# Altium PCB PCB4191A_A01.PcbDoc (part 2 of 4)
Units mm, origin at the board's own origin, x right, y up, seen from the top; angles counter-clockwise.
Board outline 160 x 160 mm, 6 copper layers (Top Layer, IM1 RIS, IM2 Signal, IM3 Signal, IM4 GND, Bottom Layer), stack 1.582 mm thick; 176 components, 121 nets, 494 pads, 4954 vias.
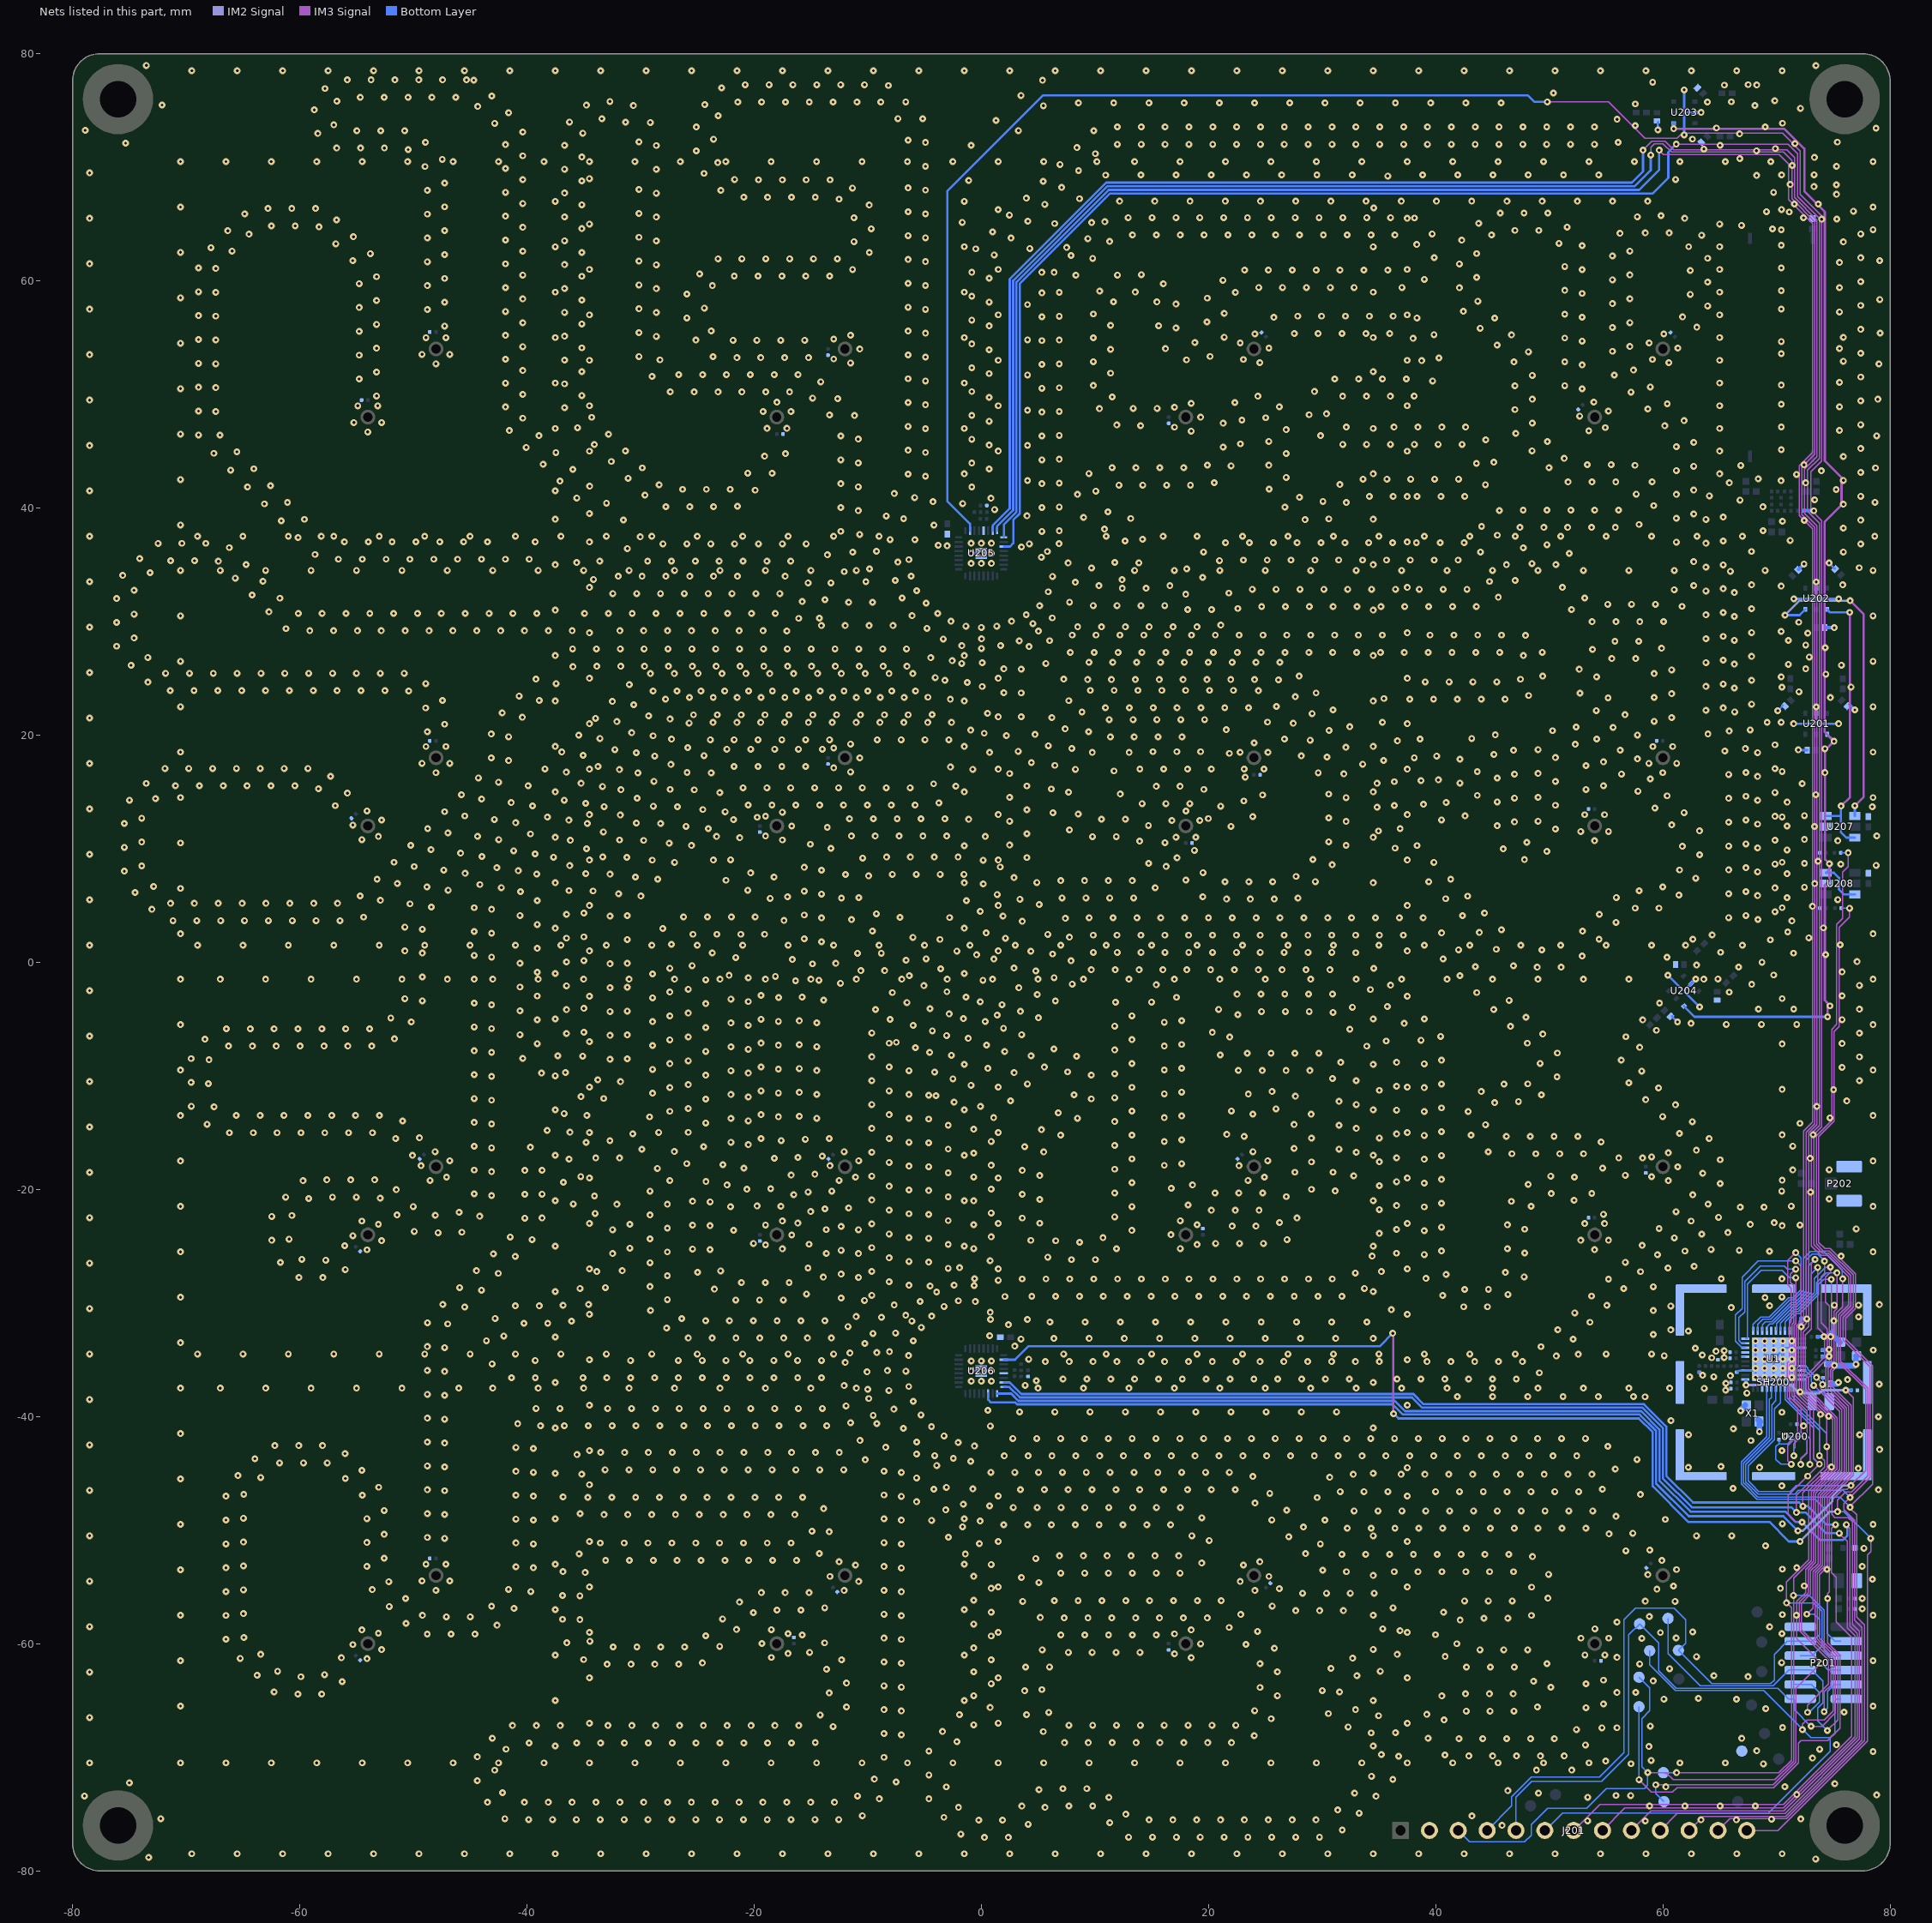
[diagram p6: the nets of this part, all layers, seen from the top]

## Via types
v1: diameter 0.6, hole 0.25, IM4 GND to Bottom Layer, tented bottom, 3924 vias
v2: diameter 0.6, hole 0.25, Top Layer to Bottom Layer, tented both sides, 851 vias
v3: diameter 0.6, hole 0.25, IM4 GND to Bottom Layer, tented both sides, 179 vias

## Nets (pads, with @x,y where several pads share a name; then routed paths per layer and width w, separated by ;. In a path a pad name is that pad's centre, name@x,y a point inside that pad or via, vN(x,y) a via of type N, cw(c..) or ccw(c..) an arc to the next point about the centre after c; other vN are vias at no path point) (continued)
CP/DP-: U201.4 U203.4 U204.4 U208.3 U208.6 | length 111
  IM3 Signal w0.2: v2(60.951,73.392) 70.683,73.392 72.45,71.625 72.45,67.876 74.251,66.075 74.251,44.149 75.725,42.675 75.725,40.25 74.23,38.755 74.23,20.291 v2(75.066,19.455) 74.275,18.665 74.275,9.044 v2(74.655,8.664) 74.655,7.192 74.25,6.787 74.25,-3.35 74.5,-3.6 v2(74.5,-4.8)
  Bottom Layer w0.2: U204.4@61.855,-3.866 62.788,-4.8 v2(74.5,-4.8) ; U201.4@74.45,20.071 v2(75.066,19.455) ; v2(74.655,8.664) 74.655,8.177 U208.3@74.355,7.878 75.06,7.878 75.496,7.441 75.496,6.41 75.933,5.973 U208.6@76.895,5.973
  Bottom Layer w0.35: v2(60.951,73.392) U203.4@60.951,73.875
CTRL1: J201.7 U1.1 U205.7 U206.7 | length 355.9
  IM3 Signal w0.1: J201.7@52.15,-76.45 54.45,-74.15 70.6,-74.15 76.6,-68.15 76.6,-59.45 75.25,-58.1 75.25,-54.15 74.854,-53.754 74.854,-49.871 v2@75.175,-49.55 ; v2(58.25,71.5) 59.025,72.275 60.2,72.275 60.95,71.525 70.925,71.525 71.6,70.85 71.6,67.325 73.568,65.357 73.568,44.518 72.475,43.425 72.475,39.525 73.568,38.432 73.568,-14.29 72.825,-15.033 72.825,-32.075 72.35,-32.55 72.35,-35.875 72.198,-36.027 72.198,-37.804 74.425,-40.03 v2(74.425,-42.65) ; v2(72.325,-47.9) 72.325,-46.725 74.45,-44.6 74.45,-42.922 v2@74.475,-42.897
  Bottom Layer w0.1: U1.1@71.55,-37.445 71.55,-38.625 74.425,-41.5 v2(74.425,-42.65)
  Bottom Layer w0.2: U205.7@1,37.985 1,38.45 2.5,39.95 2.5,60.138 11.012,68.65 57.275,68.65 58.25,69.625 v2(58.25,71.5) ; U206.7@1.985,-37 2.499,-37 3.524,-38.025 38.039,-38.025 38.929,-38.915 58.323,-38.915 60.303,-40.894 60.303,-45.228 62.65,-47.575 72,-47.575 v2(72.325,-47.9) 72.775,-47.9 74.4,-49.525 v2(75.2,-49.525)
CTRL2: J201.8 U1.2 U205.8 U206.8 | length 354
  IM3 Signal w0.1: J201.8@54.69,-76.45 56.665,-74.475 70.617,-74.475 76.9,-68.192 76.9,-59.3 76.225,-58.625 76.225,-51 v2@75.5,-50.275 ; v2(58.925,71.075) 58.95,71.1 58.95,71.75 59.25,72.05 60.025,72.05 60.75,71.325 70.625,71.325 71.35,70.6 71.35,67.225 73.368,65.207 73.368,44.725 72.25,43.607 72.25,39.4 73.368,38.282 73.368,-14.207 72.6,-14.975 72.6,-31.825 72.15,-32.275 72.15,-35.75 71.998,-35.902 71.998,-37.887 73.775,-39.663 73.775,-43.441 v2(73.782,-43.448) 73.798,-43.448 74.25,-43.9 74.25,-44.45 71.75,-46.95 v2(71.75,-48.45)
  Bottom Layer w0.1: U1.2@71.15,-37.445 71.15,-38.6 73.775,-41.225 v2@73.775,-43.45
  Bottom Layer w0.2: U205.8@1.4,37.985 1.4,38.4 2.8,39.8 2.8,60.014 11.111,68.325 57.525,68.325 58.925,69.725 v2(58.925,71.075) ; U206.8@1.985,-37.4 2.475,-37.4 3.399,-38.325 36.117,-38.325 37.915,-38.325 38.805,-39.215 58.199,-39.215 60.003,-41.018 60.003,-45.453 62.55,-48 71.3,-48 v2(71.75,-48.45) 72.55,-48.45 74.375,-50.275 v2(75.525,-50.275)
CTRL3: J201.9 U1.3 U205.9 U206.9 | length 356.4
  IM3 Signal w0.1: J201.9@57.23,-76.45 58.955,-74.725 70.65,-74.725 77.1,-68.275 77.1,-59.1 76.475,-58.475 76.475,-49.85 v2(76.15,-49.525) ; v2(59.675,71.5) 60.05,71.125 70.25,71.125 71.075,70.3 71.075,67.15 73.168,65.057 73.168,44.9 72,43.732 72,39.325 73.168,38.157 73.168,-14.082 72.4,-14.85 72.4,-31.7 71.95,-32.15 71.95,-35.625 71.798,-35.777 71.798,-37.969 73.25,-39.421 73.25,-43.66 v2(73.782,-44.192) 71.025,-46.949 71.025,-48.625 71.7,-49.3 v2(72.25,-49.3)
  Bottom Layer w0.1: U1.3@70.75,-37.445 70.75,-38.5 73.25,-41 73.25,-43.7 v2@73.75,-44.2
  Bottom Layer w0.2: U206.9@1.4,-37.985 2.635,-37.985 3.275,-38.625 36.4,-38.625 37.3,-39.525 58.085,-39.525 59.703,-41.142 59.703,-45.653 62.425,-48.375 70.775,-48.375 71.7,-49.3 v2(72.25,-49.3) 73.825,-50.875 75.85,-50.875 76.225,-50.5 76.225,-49.625 76.15,-49.55 v2(76.15,-49.525) ; U205.9@1.985,37.4 1.985,38.535 3.1,39.65 3.1,59.89 11.21,68 57.9,68 59.675,69.775 v2(59.675,71.5)
CTRL4: J201.10 U1.4 U205.11 U206.11 | length 372.8
  IM3 Signal w0.1: J201.10@59.77,-76.45 61.27,-74.95 70.75,-74.95 77.3,-68.4 77.3,-58.925 76.675,-58.3 76.675,-49.25 76.325,-48.9 75.15,-48.9 74.875,-48.625 74.875,-47.375 75.825,-46.425 76.2,-46.425 v2(76.55,-46.075) 76.55,-46.05 77.854,-44.746 77.854,-37.604 75.45,-35.2 75.45,-31.075 76.35,-30.175 76.35,-27.683 74.492,-25.825 73.925,-25.825 73.075,-24.975 73.075,-15.075 73.768,-14.382 73.768,38.657 72.725,39.7 72.725,43.332 73.768,44.375 73.768,65.507 71.85,67.425 71.85,71.2 71.025,72.025 v2(61.175,72.025)
  IM2 Signal w0.2: v2(71.888,-50.063) 72.312,-50.063 74.925,-47.45 74.925,-47.02 75.87,-46.075 v2(76.55,-46.075)
  Bottom Layer w0.1: U1.4@70.35,-37.445 70.35,-38.785 69.83,-39.306 69.83,-42.032 67.51,-44.352 67.51,-45.678 67.847,-46.015 68.431,-46.6 71.225,-46.6 71.75,-46.075 v2(76.55,-46.075)
  Bottom Layer w0.2: U206.11@0.6,-37.985 0.6,-38.525 0.841,-38.766 2.992,-38.766 3.151,-38.925 36.225,-38.925 37.125,-39.825 57.961,-39.825 59.403,-41.267 59.403,-45.903 62.275,-48.775 70.6,-48.775 v2(71.888,-50.063) ; U205.11@1.985,36.6 2.525,36.6 2.82,36.895 2.82,38.945 3.4,39.525 3.4,59.765 11.309,67.675 59.075,67.675 60.475,69.075 60.475,71.325 v2(61.175,72.025)
CTRL5: J201.11 R206.1 U1.5 | length 122.5
  IM3 Signal w0.1: J201.11@62.31,-76.45 63.56,-75.2 70.809,-75.2 77.525,-68.484 77.525,-58.575 76.875,-57.925 76.875,-49.125 75.925,-48.175 75.925,-47.675 v2(76.475,-47.125) ; v2(76.313,9.639) 76.313,8.413 75.837,7.938 75.837,3.862 75.3,3.325 75.3,-5.475 74.86,-5.915 74.86,-13.93 73.5,-15.29 73.5,-24.8 74.125,-25.425 74.658,-25.425 76.75,-27.517 76.75,-30.392 75.85,-31.292 75.85,-33.233 76.817,-34.2 78.254,-35.636 78.254,-45.371 v2@76.475,-47.15
  Bottom Layer w0.1: U1.5@69.95,-37.445 69.95,-38.623 69.604,-38.97 69.604,-41.921 67.31,-44.216 67.31,-45.761 67.537,-45.989 67.626,-46.077 68.369,-46.821 71.629,-46.821 71.95,-46.5 75.85,-46.5 v2@76.45,-47.1 ; R206.1@75.655,9.639 v2(76.313,9.639)
CTRL5+: U202.6 U207.4 | length 28
  IM3 Signal w0.2: v2(76.481,31.837) 77.675,30.643 77.675,14.559 v2(76.895,13.779)
  IM2 Signal w0.2: v2(70.758,30.566) 72.029,31.837 v2(76.481,31.837)
  Bottom Layer w0.2: v2(70.758,30.566) 72.045,30.566 U202.6@72.55,31.071 ; U207.4@76.895,12.878 v2(76.895,13.779)
CTRL5-: U202.4 U207.3 U207.6 | length 24.5
  IM3 Signal w0.2: v2(75.689,13.752) 76.47,14.534 v2@76.47,30.807
  Bottom Layer w0.2: U207.3@74.355,12.878 75.66,12.878 ; U202.4@74.45,31.071 74.715,30.807 v2(76.442,30.807) ; v2(75.689,13.752) 75.66,13.723 75.66,12.878 ; U207.6@76.895,10.973 76.153,10.973 75.66,11.465 75.66,12.878
CTRL6: J201.12 R207.1 U1.6 | length 115.3
  IM3 Signal w0.1: J201.12@64.85,-76.45 65.9,-75.4 70.892,-75.4 77.75,-68.542 77.75,-58.35 77.075,-57.675 77.075,-48.662 76.475,-48.062 v2(76.475,-48) 76.475,-47.938 78.454,-45.959 78.454,-35.554 76.9,-34 76.075,-33.175 76.075,-31.375 76.95,-30.5 76.95,-27.434 74.741,-25.225 74.275,-25.225 73.725,-24.675 73.725,-15.348 75.06,-14.013 75.06,-6.115 75.525,-5.65 75.525,3.05 76.435,3.96 v2(76.435,4.76)
  Bottom Layer w0.1: U1.6@69.55,-37.445 69.55,-38.329 69.373,-38.506 69.373,-41.851 67.11,-44.114 67.11,-45.844 67.245,-45.979 68.348,-47.082 75.582,-47.082 76.475,-47.975 v2(76.475,-48) ; R207.1@75.694,4.76 v2(76.435,4.76)
CTRL7: J201.13 U1.7 U205.2 U206.2 | length 382.4
  IM3 Signal w0.1: v2(49.825,75.75) 55.225,75.75 58.425,72.55 61.25,72.55 61.7,73 70.525,73 72.1,71.425 72.1,67.605 73.98,65.725 73.98,44.125 73.025,43.17 73.025,39.85 73.98,38.895 73.98,-14.47 73.275,-15.175 73.275,-24.858 74.042,-25.625 74.575,-25.625 76.55,-27.6 76.55,-30.275 75.65,-31.175 75.65,-35.117 78.054,-37.521 78.054,-45.221 76.625,-46.65 76.1,-46.65 75.375,-47.375 v2(75.375,-48.375) ; J201.13@67.39,-76.45 J201.13@67.392,-76.45 70.125,-76.45 78,-68.575 78,-52.2 78.3,-51.9 v2(78.3,-50.725)
  IM3 Signal w0.2: v2(36.225,-32.675) 36.275,-32.725 36.275,-39.725 v2(36.3,-39.75)
  IM2 Signal w0.2: v2(72.075,-51) 74.7,-48.375 v2(75.375,-48.375)
  Bottom Layer w0.1: U1.7@69.15,-37.445 69.15,-41.765 66.91,-44.006 66.91,-45.927 68.286,-47.303 73.411,-47.303 74.484,-48.375 v2(75.375,-48.375) 75.95,-48.375 v2(78.3,-50.725)
  Bottom Layer w0.2: U205.2@-1,37.985 -1,38.6 -3.001,40.6 -3.001,67.894 5.443,76.338 48.113,76.338 48.7,75.75 v2(49.825,75.75) ; U206.2@1.985,-35 2.973,-35 4.174,-33.8 35.1,-33.8 v2(36.225,-32.675) ; v2(36.3,-39.75) 36.725,-40.175 57.887,-40.175 59.103,-41.391 59.103,-46.153 62.225,-49.275 69.375,-49.275 71.1,-51 v2(72.075,-51)
EFR32_#RESET: C208.1 P201.3 TPJ17.1 U1.11 | length 74.1
  IM3 Signal w0.1: v2(57.899,-71.975) 58.999,-73.075 60.85,-73.075 61.25,-72.675 69.751,-72.675 71.923,-70.503 71.923,-68.767 72.142,-68.548 74.487,-68.548 75.593,-67.441 75.593,-61.016 74.5,-59.923 v2(74.5,-56.023) 74.5,-55.607 74.654,-55.453 74.654,-47.271 76.758,-45.167 76.758,-38.338 v2(76.105,-37.686)
  IM2 Signal w0.2: v2(67.325,-37.231) 71.281,-37.231 72,-37.95 73.775,-37.95 74.039,-37.686 v2(76.105,-37.686)
  Bottom Layer w0.1: v2(57.899,-71.975) TPJ17.1@57.899,-65.557 ; v2(74.5,-56.023) 74.459,-56.064 74.459,-59.117 75.124,-59.782 P201.3@75.657,-59.782 ; C208.1@76.577,-37.686 C208.1@76.615,-37.648
  Bottom Layer w0.3: v2(67.325,-37.231) 67.325,-37.226 67.4,-37.151 67.325,-37.076 U1.11@67.325,-36.842 ; v2(76.105,-37.686) C208.1@76.577,-37.686
EFR32_PA00: R205.1 U1.21 U200.A3 | length 34.1
  IM3 Signal w0.1: v2@71.275,-44.175 71,-43.9 71,-42.575 71.875,-41.7 71.875,-39.3 70.95,-38.375 70.95,-35.3 71.125,-35.125 71.125,-31.826 71.3,-31.651 71.3,-28.7 70.975,-28.375 70.975,-26.275 71.675,-25.575 v2(71.7,-25.575)
  Bottom Layer w0.1: U1.21@67.95,-32.455 67.95,-31.9 68.601,-31.25 69.375,-31.25 71.077,-29.548 71.452,-29.548 72.175,-28.825 72.175,-26.05 v2(71.7,-25.575) ; 70.225,-42.35 R205.1@70.225,-42.025 ; U200.A3@71.25,-42.125 70.975,-42.4 70.225,-42.4 70.225,-42.375 69.95,-42.65 69.95,-43.775 70.375,-44.2 v2(71.3,-44.2)
EFR32_PA01: P201.8 TPJ2.1 U1.22 | length 80.6
  IM3 Signal w0.1: v2(74.474,-67.643) 75.393,-66.724 75.393,-61.099 73.8,-59.506 73.8,-53.915 74.454,-53.261 74.454,-47.188 76.558,-45.084 76.558,-39.008 74.95,-37.4 74.95,-35.975 75.25,-35.675 75.25,-30.9 75.825,-30.325 v2(75.825,-27.875) 75.8,-27.875 v2@75.775,-27.85
  Bottom Layer w0.1: TPJ2.1@60.449,-57.777 60.449,-60.876 63.293,-63.719 69.688,-63.719 71.086,-62.322 P201.8@72.093,-62.322 73.107,-62.322 74.082,-63.296 74.082,-65.232 73.628,-65.686 73.628,-66.797 v2(74.474,-67.643) ; U1.22@68.35,-32.455 68.35,-31.9 68.8,-31.45 69.475,-31.45 71.177,-29.748 71.534,-29.748 72.4,-28.883 72.4,-26.075 73,-25.475 74.175,-25.475 75.8,-27.1 75.8,-27.875 v2(75.825,-27.875)
EFR32_PA02: P201.7 TPJ1.1 U1.23 | length 76.8
  IM3 Signal w0.1: v2(59.375,-72.425) 69.715,-72.425 69.716,-72.427 71.714,-70.429 71.714,-63.937 v2(73.908,-61.742) 73.908,-61.679 71.79,-59.56 71.79,-56.273 72.56,-55.504 72.56,-53.458 73.254,-52.764 73.254,-46.691 75.344,-44.601 75.344,-40.099 72.8,-37.555 72.8,-36.55 74.45,-34.9 74.45,-32.275 73.925,-31.75 73.925,-27.7 74.225,-27.4 v2(74.225,-26.325)
  Bottom Layer w0.1: v2(59.375,-72.425) 59.375,-73.185 TPJ1.1@60.098,-73.907 ; U1.23@68.75,-32.455 68.75,-31.917 69.018,-31.65 69.575,-31.65 71.277,-29.948 71.617,-29.948 72.625,-28.941 72.625,-26.225 73.15,-25.7 73.625,-25.7 74.225,-26.3 v2(74.225,-26.325) ; v2(73.908,-61.742) 73.972,-61.742 74.551,-62.322 P201.7@75.657,-62.322
EFR32_PA03: P201.6 TPJ3.1 U1.24 | length 76.2
  IM3 Signal w0.1: v2@61.205,-71.377 70.198,-71.377 71.312,-70.263 71.312,-56.851 v2(70.88,-56.418) 70.88,-54.57 72.852,-52.598 72.852,-46.525 74.942,-44.435 74.942,-40.265 72.398,-37.721 72.398,-36.202 72.55,-36.05 72.55,-32.825 73.075,-32.3 73.075,-26.5 v2(73.4,-26.175)
  Bottom Layer w0.1: TPJ3.1@60.049,-71.357 v2(61.205,-71.357) ; U1.24@69.15,-32.455 69.2,-32.405 69.2,-32.05 69.4,-31.85 69.675,-31.85 71.377,-30.148 71.7,-30.148 72.85,-28.999 72.85,-26.725 v2(73.4,-26.175) ; v2(70.88,-56.418) 73.259,-56.418 73.993,-57.151 73.993,-60.182 73.123,-61.052 P201.6@72.093,-61.052
EFR32_PA04: U1.25
EFR32_PA05: J201.3 P201.5 TPJ5.1 U1.26 | length 106.5
  IM3 Signal w0.102: v2(58.665,-71.349) 60.274,-71.349 60.911,-71.986 69.873,-71.986 71.513,-70.346 71.513,-54.221 73.053,-52.681 73.053,-46.608 75.143,-44.518 75.143,-40.182 72.599,-37.638 72.599,-36.4 74.249,-34.751 74.249,-32.799 73.625,-32.175 v2(73.625,-26.875)
  Bottom Layer w0.102: J201.3@41.99,-76.45 42.99,-77.45 47.825,-77.45 48.4,-76.875 48.4,-75.95 49.868,-74.482 53.293,-74.482 55.025,-72.75 58.375,-72.75 58.665,-72.46 v2(58.665,-71.349) 58.153,-70.837 58.153,-66.598 58.841,-65.91 58.841,-63.899 TPJ5.1@57.899,-62.957 ; U1.26@70,-32.405 70,-31.825 71.476,-30.349 71.783,-30.349 73.075,-29.057 73.075,-27.425 v2(73.625,-26.875) ; v2(71.489,-55.749) 72.875,-55.749 74.194,-57.069 74.194,-60.578 74.667,-61.052 P201.5@75.657,-61.052
EFR32_PA06: J201.4 P201.4 TPJ6.1 U1.27 | length 96.5
  IM3 Signal w0.1: v2(72.676,-57.403) 73.2,-56.879 73.2,-53.666 73.854,-53.013 73.854,-46.94 75.958,-44.836 75.958,-39.316 74.35,-37.708 74.35,-35.709 74.65,-35.409 74.65,-30.267 74.3,-29.917 74.3,-27.75 74.75,-27.3 v2(74.75,-26.85)
  Bottom Layer w0.1: J201.4@44.53,-76.45 46.699,-74.281 46.699,-73.463 48.412,-71.75 54.425,-71.75 56.575,-69.6 56.575,-57.9 57.6,-56.875 60.975,-56.875 62,-57.9 62,-59.957 TPJ6.1@61.369,-60.587 64.297,-63.515 69.499,-63.515 69.802,-63.212 69.802,-60.943 70.963,-59.782 P201.4@72.093,-59.782 73.191,-59.782 73.768,-59.206 73.768,-57.87 73.301,-57.403 v2(72.676,-57.403) ; U1.27@70.35,-32.455 70.35,-31.767 71.567,-30.55 71.866,-30.55 73.325,-29.091 73.325,-27.85 74.325,-26.85 v2(74.75,-26.85)
EFR32_PA07: J201.5 P201.12 TPJ8.1 U1.28 | length 98.9
  IM3 Signal w0.1: v2(73.051,-67.276) 74.015,-67.276 75.193,-66.098 75.193,-61.182 73.6,-59.589 73.6,-53.832 74.254,-53.178 74.254,-47.105 76.358,-45.002 76.358,-39.108 74.75,-37.5 74.75,-35.875 75.05,-35.575 75.05,-30.75 75.325,-30.475 v2(75.325,-27.35)
  Bottom Layer w0.1: J201.5@47.07,-76.45 47.07,-73.511 48.456,-72.125 54.6,-72.125 56.975,-69.75 56.975,-59.232 TPJ8.1@57.949,-58.257 59.632,-59.939 59.632,-62.371 61.18,-63.919 70.116,-63.919 71.058,-64.862 71.593,-64.862 71.593,-65.836 73.033,-67.276 v2(73.051,-67.276) ; U1.28@70.75,-32.403 70.75,-31.65 71.65,-30.75 71.949,-30.75 73.525,-29.174 73.525,-28.225 74.4,-27.35 v2(75.325,-27.35)
EFR32_PA08: J201.6 P201.11 TPJ7.1 U1.29 | length 103.9
  IM3 Signal w0.1: v2(72.284,-67.571) 72.284,-67.099 72.671,-66.712 74.205,-66.712 74.993,-65.924 74.993,-61.265 73.4,-59.672 73.4,-53.749 74.054,-53.095 74.054,-47.023 76.158,-44.919 76.158,-39.233 74.825,-37.9 74.825,-37.858 74.55,-37.583 74.55,-35.792 74.85,-35.492 74.85,-27.95 v2(74.825,-27.925)
  Bottom Layer w0.1: J201.6@49.61,-76.45 51.159,-74.901 69.299,-74.901 74.728,-69.472 74.728,-68.287 ; TPJ7.1@58.839,-60.627 58.839,-61.862 61.097,-64.119 68.879,-64.119 73.046,-68.287 74.728,-68.287 ; U1.29@71.15,-32.455 71.15,-31.55 71.75,-30.95 72.032,-30.95 73.725,-29.257 73.725,-28.35 74.15,-27.925 v2(74.825,-27.925) ; P201.11@75.657,-64.862 75.275,-64.862 75.129,-65.008 75.129,-67.886 74.728,-68.287
EFR32_PB00: U1.20 U200.D2 | length 30.7
  IM3 Signal w0.1: v2(71.7,-27.775) 71.7,-31.817 71.55,-31.967 71.55,-35.375 71.379,-35.546 71.379,-38.179 72.7,-39.5 72.7,-43.175 72.125,-43.75 v2(72.125,-44.225)
  Bottom Layer w0.1: U1.20@67.255,-33.15 67.45,-33.15 67.45,-28.325 68.65,-27.125 70.5,-27.125 71.15,-27.775 v2(71.7,-27.775) ; U200.D2@71.85,-41.775 72.3,-41.775 72.675,-42.15 72.675,-43.2 72.125,-43.75 v2(72.125,-44.225)
EFR32_PB01: U1.19 U200.C3 | length 30.2
  IM3 Signal w0.1: v2(71.525,-43.45) 71.525,-42.4 72.175,-41.75 72.175,-39.275 71.15,-38.25 71.15,-35.475 71.35,-35.275 71.35,-31.884 71.5,-31.734 71.5,-28.45 71.225,-28.175 71.225,-27.475 71.675,-27.025 v2(71.7,-27.025)
  Bottom Layer w0.1: U1.19@67.255,-33.55 66.925,-33.55 66.675,-33.3 66.675,-31.3 67.2,-30.775 67.2,-28.125 68.575,-26.75 70.675,-26.75 70.95,-27.025 v2(71.7,-27.025) ; v2(71.525,-43.45) 71.525,-42.85 71.65,-42.725 U200.C3@71.65,-42.125
EFR32_PB02: U1.18 U200.E1 | length 34.6
  IM3 Signal w0.1: v2(71.7,-26.3) 71.725,-26.3 72.175,-26.75 72.175,-31.625 71.75,-32.05 71.75,-35.5 71.598,-35.652 71.598,-38.052 71.6,-38.054 71.6,-38.1 72.95,-39.45 v2(72.95,-44.225)
  Bottom Layer w0.1: U1.18@67.255,-33.95 67.206,-33.9 66.9,-33.9 66.375,-33.375 66.375,-31.075 66.975,-30.475 66.975,-27.725 68.4,-26.3 v2(71.7,-26.3) ; U200.E1@72.05,-41.425 72.4,-41.425 72.95,-41.975 v2(72.95,-44.225)
EFR32_PB03: U1.17
EFR32_PB04: U1.16 | length 0.3
  Bottom Layer w0.1: U1.16@66.97,-34.75 U1.16@67.255,-34.75
EFR32_PC07: U1.8
EFR32_PD00: U1.40 X2.1 | length 1.9
  Bottom Layer w0.1: U1.40@72.245,-36.75 72.5,-36.75 72.5,-36.756 72.51,-36.766 72.55,-36.806 72.55,-37.756 72.92,-38.125 X2.1@73,-38.125
EFR32_PD01: U1.39 X2.2 | length 3.4
  Bottom Layer w0.1: U1.39@72.245,-36.35 72.531,-36.35 72.8,-36.619 72.8,-37.506 73.075,-37.781 74.05,-37.781 X2.2@74.385,-38.115
EFR32_PD02: P201.10 U1.38 | length 39.9
  IM3 Signal w0.1: v2(72.737,-66.043) 72.737,-65.425 74.593,-63.569 74.593,-61.431 71.99,-58.827 71.99,-56.359 72.8,-55.548 72.8,-53.5 73.454,-52.847 73.454,-46.774 75.558,-44.67 75.558,-39.538 v2(73.275,-37.256)
  Bottom Layer w0.1: P201.10@71.593,-63.592 P201.10@72.093,-63.592 73.059,-63.592 73.78,-64.313 73.78,-65.121 72.858,-66.043 v2(72.737,-66.043) ; U1.38@72.245,-35.95 72.545,-35.95 73.05,-36.456 73.05,-36.931 v2@73.248,-37.128 ; v2@73.225,-37.1 73.25,-37.125 v2@73.248,-37.128 ; v2@73.25,-37.131 v2@73.248,-37.128 ; v2(73.275,-37.256) 73.275,-37.242 73.306,-37.273 73.325,-37.253 73.224,-37.152 v2@73.248,-37.128
EFR32_PD03: P201.9 U1.37 | length 38.1
  IM3 Signal w0.1: v2(73.525,-36.556) 73.914,-36.944 73.914,-37.564 75.758,-39.408 75.758,-44.753 73.654,-46.857 73.654,-52.93 73,-53.583 73,-55.631 72.19,-56.441 72.19,-58.745 74.793,-61.348 74.793,-63.652 74.2,-64.245 v2(74.2,-65.986)
  Bottom Layer w0.1: U1.37@72.245,-35.55 72.57,-35.55 72.775,-35.756 72.775,-35.856 73.35,-36.431 v2@73.45,-36.431 ; v2@73.3,-36.456 v2@73.325,-36.481 ; v2(74.2,-65.986) 74.5,-65.685 74.5,-64.183 75.092,-63.592 P201.9@75.657,-63.592
GND: C1.2 C2.2 C3.2 C11.1 C21.1 C201.2 C202.2 C203.2 C204.2 C205.2 C206.2 C207.2 C208.2 C209.2 C210.2 C211.2 C212.2 C213.2 C214.2 C215.2 C216.2 C217.2 C218.2 C219.1 C220.1 C221.1 C222.1 C223.1 C224.1 CH1.2 CH2.2 CH3.2 CH4.2 CH5.2 CH6.2 CH7.2 CH8.2 CH9.2 CH10.2 CH11.2 CH12.2 CH13.2 CH14.2 CH15.2 CH16.2 CV1.2 CV2.2 CV3.2 CV4.2 CV5.2 CV6.2 CV7.2 CV8.2 CV9.2 CV10.2 CV11.2 CV12.2 CV13.2 CV14.2 CV15.2 CV16.2 D11.1 D12.1 D13.1 D21.1 D22.1 D23.1 D31.1 D32.1 D33.1 D41.1 D42.1 D43.1 J201.2 LED1.1 P201.2 P202.2 P202.3 RDH2.2 RH1.2 SH200.1 TPJ13.1 U1.0 U1.13 U1.33 U200.B2 U201.2 U201.7 U202.2 U202.7 U203.2 U203.7 U204.2 U204.7 U205.0 U205.5 U206.0 U206.5 U207.2 U208.2 X1.2 X1.4 | length 66.6
  Bottom Layer w0.1: v3(70.11,22.138) D12.1@70.63,22.658 ; v1@73.1,39.753 v1(73.286,39.753) ; v3@74.05,-37.206 74.1,-37.156 C213.2@74.1,-36.581 ; v2@75.325,-37.131 v2@75.425,-37.031
  Bottom Layer w0.2: v3(59.564,73.287) 59.564,73.947 59.582,73.965 D33.1@59.6,73.983 ; v3(60.44,-1.138) 61.717,-2.415 ; D43.1@60.823,-4.746 60.823,-4.796 v3(61.29,-5.263) ; v3(61.88,72.845) 61.88,74.675 ; 61.88,74.999 v3(61.88,76.805) ; 61.946,-2.644 v3(63.24,-3.938) ; 61.946,-2.432 U204.2@62.497,-1.881 v3(62.89,-1.488) ; 62.03,74.825 U203.2@62.809,74.825 v3(63.365,74.825) ; v3(63.609,71.604) v3@63.7,71.695 ; C1.2@66.525,-36.075 66.6,-36.075 66.725,-35.95 U1.13@67.255,-35.95 67.95,-35.95 v3(68.15,-35.75) ; v3(68.15,-33.35) v3(68.15,-34.15) v2(68.15,-34.95) v3(68.15,-35.75) ; v3(68.95,-33.35) v3(68.95,-34.15) v3(68.95,-34.95) v3(68.95,-35.75) v3(68.95,-36.55) ; v3(69.75,-33.35) v3(69.75,-34.15) v3(69.75,-34.95) ; v2(70.55,-33.35) v3(70.55,-34.15) ; v1(70.8,-41.725) 70.85,-41.775 U200.B2@71.45,-41.775 ; v3(71.35,-33.35) U1.0@71.35,-33.95 ; v3(71.516,21) 73.35,21 73.5,21.15 73.65,21 v3(75.475,21) ; v3(71.521,32) 73.324,32 ; v3(71.925,18.7) 71.95,18.675 D13.1@72.71,18.675 ; U1.33@72.245,-33.95 U1.0@71.35,-33.95 ; 73.475,21.425 73.495,21.445 v3(73.495,22.485) ; v3(73.5,33.485) U202.2@73.5,32.929 73.5,32.15 73.65,32 v3(75.48,32) ; v3(74.628,35.151) D21.1@75.13,34.648 ; D11.1@76.408,22.692 76.433,22.692 v3(76.9,22.225) ; v3(68.15,-35.75) v3(68.15,-36.55) v3(68.95,-36.55) ; v3(68.95,-36.55) v2(69.75,-36.55) ; v2(69.75,-36.55) v3(69.75,-35.75) v3(69.75,-34.95) ; v2(69.75,-36.55) v3(70.55,-36.55) v3(71.35,-36.55) v3(71.35,-35.75) v3(71.35,-34.95) v3(71.35,-34.15) U1.0@71.35,-33.95 ; v3(69.75,-34.95) v3(70.55,-34.15) ; v3(70.55,-34.15) 70.75,-33.95 U1.0@71.35,-33.95 ; 73.324,32 73.325,32.001
  Bottom Layer w0.25: C3.2@63.325,-36.2 v3(63.5,-36.375)
  Bottom Layer w0.3: C3.2@63.2,-36.1 63.476,-36.375 v3(63.5,-36.375) ; v3(70.55,-36.55) v3(70.55,-35.75) v2(70.55,-34.95) v3(70.55,-34.15) ; D22.1@71.953,34.589 v3(72.426,35.062) v3@72.443,35.08 ; v3@72.125,-32.081 C217.2@72.125,-31.675 72.125,-31.35 72.625,-31.35 v3(72.675,-31.4) ; RDH2.2@72.417,39.753 v1@73.1,39.753 ; C209.2@73.625,-32.981 73.65,-32.956 v3(74.175,-32.956) 74.419,-32.956 75.05,-32.325 ; C211.2@74.025,-34.725 74.606,-34.725 v3(74.625,-34.706) ; C216.2@74.025,-34.15 74.581,-34.15 v3(74.625,-34.106) ; v3@74.04,-37.131 v3@74.05,-37.141 ; v3@74.043,-37.131 74.05,-37.137 v3@74.05,-37.141 ; v3(74.05,-37.181) v3@74.05,-37.141 ; D23.1@74.343,29.437 74.36,29.455 v3(75.091,29.455) ; v3@74.825,-32.975 75.05,-32.75 75.05,-32.325 ; v3(75.05,-31.575) 75.05,-32.325
  Bottom Layer w0.5: v1(66.848,-39.498) 66.848,-39.408 X1.2@67.25,-39.006 ; v3(68.5,-41.331) 68.5,-40.55 68.575,-40.475 X1.4@68.525,-40.475 ; X1.4@68.5,-40.4 X1.4@68.45,-40.35 ; X1.4@68.55,-40.375 X1.4@68.5,-40.35 ; v3(74.175,-32.956) 74.192,-32.973 v3(74.774,-32.973) v3@74.798,-32.973 ; C212.2@74.55,-35.375 74.556,-35.381 74.984,-35.381 v3(75.103,-35.5) 75.134,-35.531 76.87,-35.531 v3(77,-35.4) C210.2@77,-34.975 ; v3(74.625,-34.706) v3(74.625,-34.106) ; C214.2@74.775,-37.131 v2@75.325,-37.131 ; v3@74.775,-32.981 75.106,-32.981 75.4,-33.275 C215.2@75.6,-33.475 ; C210.2@77,-34.675 C210.2@77.05,-34.675 ; X1.4@68.45,-40.35 X1.4@68.5,-40.35 ; X1.4@68.45,-40.35 68.4,-40.3 68.49,-40.345 X1.4@68.5,-40.35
